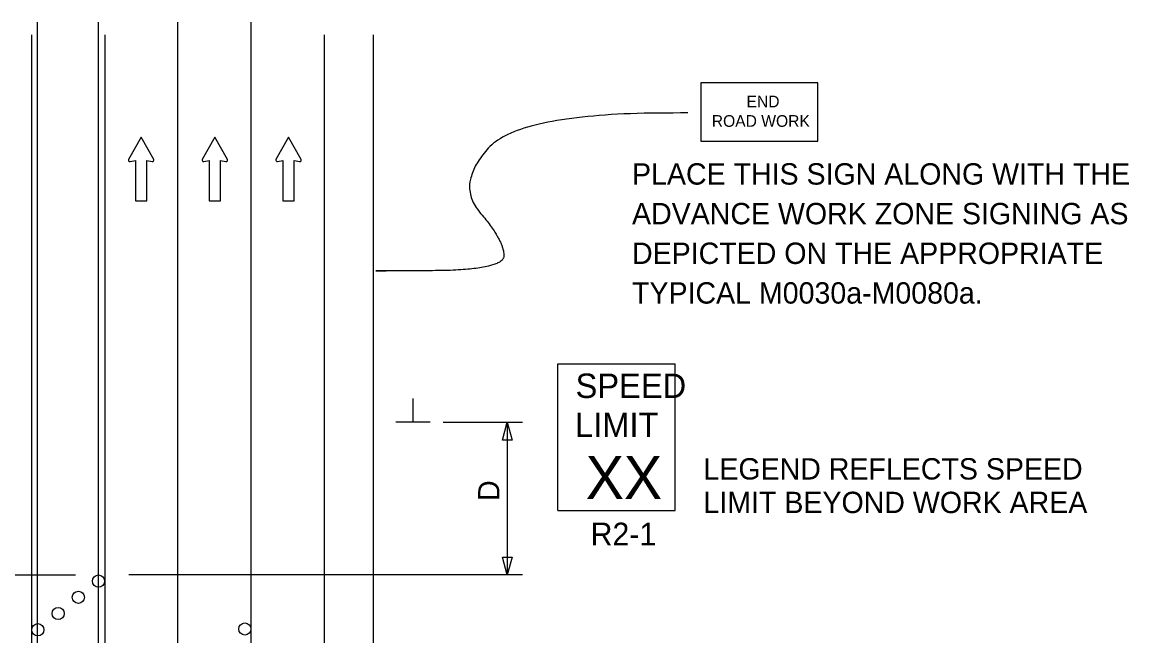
# Model space of a CAD drawing. Extents: x 16732 to 18475, y 5726 to 6929.
# Drawn here: x 17046.3 to 17409.2, y 6727.8 to 6929 of the extents above; entities that cross this region are included whole.
import ezdxf

# ---------------------------------------------------------------- set-up
doc = ezdxf.new("R2010")
doc.units = 0
for name, color, linetype in [('ALI_LEGAL_EX', 7, 'Continuous'), ('MT_SCRATCH_LEVEL_E', 7, 'Continuous'), ('PAVT_EDGE_EX', 7, 'Continuous'), ('TRAFFIC_SIGNS_PR', 7, 'Continuous'), ('TYPICAL_TEXT_DIMEN_PR', 7, 'Continuous')]:
    doc.layers.add(name, color=color, linetype=linetype)

msp = doc.modelspace()

# ---------------------------------------------------------------- linework, layer by layer
at = {"layer": 'ALI_LEGAL_EX'}
for p, q in [((17051.36, 6131.68), (17051.36, 6928.96)), ((17071.36, 6131.68), (17071.36, 6928.96)), ((17097.36, 6131.68), (17097.36, 6928.96)), ((17121.36, 6131.68), (17121.36, 6928.96))]:
    msp.add_line(p, q, dxfattribs=at)
for points in [[(17051.36, 6831.68), (17051.36, 6856.68)], [(17071.36, 6831.68), (17071.36, 6856.68)], [(17097.36, 6831.68), (17097.36, 6856.68)], [(17121.36, 6831.68), (17121.36, 6856.68)], [(17051.36, 6731.68), (17051.36, 6756.68)], [(17071.36, 6731.68), (17071.36, 6756.68)], [(17097.36, 6731.68), (17097.36, 6756.68)], [(17121.36, 6731.68), (17121.36, 6756.68)]]:
    msp.add_lwpolyline(points, dxfattribs=at)
at = {"layer": 'MT_SCRATCH_LEVEL_E'}
for p, q in [((17085.29, 6891.21), (17081.18, 6883.97)), ((17085.29, 6891.21), (17081.18, 6883.97)), ((17089.44, 6883.97), (17085.29, 6891.21)), ((17089.44, 6883.97), (17085.29, 6891.21)), ((17109.46, 6891.21), (17105.35, 6883.97)), ((17109.46, 6891.21), (17105.35, 6883.97)), ((17113.61, 6883.97), (17109.46, 6891.21)), ((17113.61, 6883.97), (17109.46, 6891.21)), ((17133.63, 6891.21), (17129.52, 6883.97)), ((17133.63, 6891.21), (17129.52, 6883.97)), ((17137.78, 6883.97), (17133.63, 6891.21)), ((17137.78, 6883.97), (17133.63, 6891.21)), ((17081.66, 6883.28), (17083.44, 6883.6)), ((17081.66, 6883.28), (17083.44, 6883.6)), ((17083.44, 6883.6), (17083.44, 6870.34)), ((17083.44, 6883.6), (17083.44, 6870.34)), ((17087.18, 6870.34), (17087.18, 6883.6)), ((17087.18, 6883.6), (17088.96, 6883.28)), ((17087.18, 6870.34), (17087.18, 6883.6)), ((17087.18, 6883.6), (17088.96, 6883.28)), ((17105.83, 6883.28), (17107.61, 6883.6)), ((17105.83, 6883.28), (17107.61, 6883.6)), ((17107.61, 6883.6), (17107.61, 6870.34)), ((17107.61, 6883.6), (17107.61, 6870.34)), ((17111.35, 6870.34), (17111.35, 6883.6)), ((17111.35, 6883.6), (17113.13, 6883.28)), ((17111.35, 6870.34), (17111.35, 6883.6)), ((17111.35, 6883.6), (17113.13, 6883.28)), ((17130, 6883.28), (17131.78, 6883.6)), ((17130, 6883.28), (17131.78, 6883.6)), ((17131.78, 6883.6), (17131.78, 6870.34)), ((17131.78, 6883.6), (17131.78, 6870.34)), ((17135.52, 6870.34), (17135.52, 6883.6)), ((17135.52, 6883.6), (17137.3, 6883.28)), ((17135.52, 6870.34), (17135.52, 6883.6)), ((17135.52, 6883.6), (17137.3, 6883.28)), ((17083.44, 6870.34), (17087.18, 6870.34)), ((17083.44, 6870.34), (17087.18, 6870.34)), ((17107.61, 6870.34), (17111.35, 6870.34)), ((17107.61, 6870.34), (17111.35, 6870.34)), ((17131.78, 6870.34), (17135.52, 6870.34)), ((17131.78, 6870.34), (17135.52, 6870.34))]:
    msp.add_line(p, q, dxfattribs=at)
for centre, start, end in [((17081.59, 6883.74), 150.4248, 279.9638), ((17081.59, 6883.74), 150.4248, 279.9638), ((17089.03, 6883.74), 260.0362, 29.7731), ((17089.03, 6883.74), 260.0362, 29.7731), ((17105.76, 6883.74), 150.4248, 279.9638), ((17105.76, 6883.74), 150.4248, 279.9638), ((17113.2, 6883.74), 260.0362, 29.7731), ((17113.2, 6883.74), 260.0362, 29.7731), ((17129.93, 6883.74), 150.4248, 279.9638), ((17129.93, 6883.74), 150.4248, 279.9638), ((17137.37, 6883.74), 260.0362, 29.7731), ((17137.37, 6883.74), 260.0362, 29.7731)]:
    msp.add_arc(centre, 0.463, start, end, dxfattribs=at)
at = {"layer": 'PAVT_EDGE_EX'}
for p, q in [((17049.36, 6924.76), (17049.36, 6059.7)), ((17073.36, 6924.76), (17073.36, 6059.7)), ((17145.36, 6924.76), (17145.36, 6059.7)), ((17161.36, 6924.76), (17161.36, 6059.7))]:
    msp.add_line(p, q, dxfattribs=at)
at = {"layer": 'TRAFFIC_SIGNS_PR'}
for p, q in [((17221.99, 6816.92), (17260.39, 6816.92)), ((17221.99, 6768.92), (17221.99, 6816.92)), ((17260.39, 6768.92), (17260.39, 6816.92)), ((17221.99, 6768.92), (17260.39, 6768.92))]:
    msp.add_line(p, q, dxfattribs=at)
msp.add_lwpolyline([(17268.81, 6889.91), (17307.21, 6889.91), (17307.21, 6909.11), (17268.81, 6909.11)], close=True, dxfattribs=at)
for centre in [(17071.35, 6745.77), (17064.72, 6740.45), (17058.09, 6735.14), (17051.45, 6729.82), (17051.46, 6729.82), (17119.33, 6730.06)]:
    msp.add_circle(centre, 2, dxfattribs=at)
at = {"layer": 'TYPICAL_TEXT_DIMEN_PR'}
for p, q in [((17174.48, 6797.8), (17174.48, 6805.59)), ((17180.11, 6797.8), (17168.86, 6797.8)), ((17184.36, 6797.8), (17210.36, 6797.8)), ((17203.79, 6791.94), (17205.36, 6797.8)), ((17205.36, 6797.8), (17205.36, 6747.8)), ((17205.36, 6797.8), (17206.93, 6791.94)), ((17205.36, 6791.94), (17203.79, 6791.94)), ((17206.93, 6791.94), (17205.36, 6791.94)), ((17205.36, 6747.8), (17203.79, 6753.66)), ((17203.79, 6753.66), (17205.36, 6753.66)), ((17205.36, 6753.66), (17206.93, 6753.66)), ((17206.93, 6753.66), (17205.36, 6747.8)), ((16912.36, 6747.8), (17063.81, 6747.8)), ((17210.36, 6747.8), (17081.31, 6747.8))]:
    msp.add_line(p, q, dxfattribs=at)
msp.add_open_spline([(17264.57, 6899.2), (17210.19, 6899.69), (17188.43, 6875.89), (17204.26, 6857.39), (17204.26, 6847.49), (17154.61, 6847.49), (17165.65, 6847.49)], degree=2, dxfattribs=at)

# ---------------------------------------------------------------- texts
at = {"layer": 'TRAFFIC_SIGNS_PR'}
for s, height, p in [('END', 3.831, (17283.81, 6901.04)), ('ROAD WORK', 3.831, (17272.42, 6894.65)), ('PLACE THIS SIGN ALONG WITH THE', 7, (17246.27, 6875.71)), ('ADVANCE WORK ZONE SIGNING AS', 7, (17246.27, 6862.71)), ('DEPICTED ON THE APPROPRIATE', 7, (17246.27, 6849.71)), ('TYPICAL M0030a-M0080a.', 7, (17246.27, 6836.71)), ('SPEED', 8, (17227.76, 6805.78)), ('LIMIT', 8, (17227.6, 6792.98)), ('XX', 14.031, (17231.1, 6772.68)), ('R2-1', 7.44, (17232.67, 6757.48))]:
    msp.add_text(s, height=height, dxfattribs=at).set_placement(p)
at = {"layer": 'TYPICAL_TEXT_DIMEN_PR'}
for s, p in [('LEGEND REFLECTS SPEED', (17269.7, 6779.05)), ('LIMIT BEYOND WORK AREA', (17269.7, 6768.05))]:
    msp.add_text(s, height=7, dxfattribs=at).set_placement(p)
msp.add_text('D', height=7, rotation=90, dxfattribs=at).set_placement((17202.8, 6772.02))

doc.saveas('drawing.dxf')
